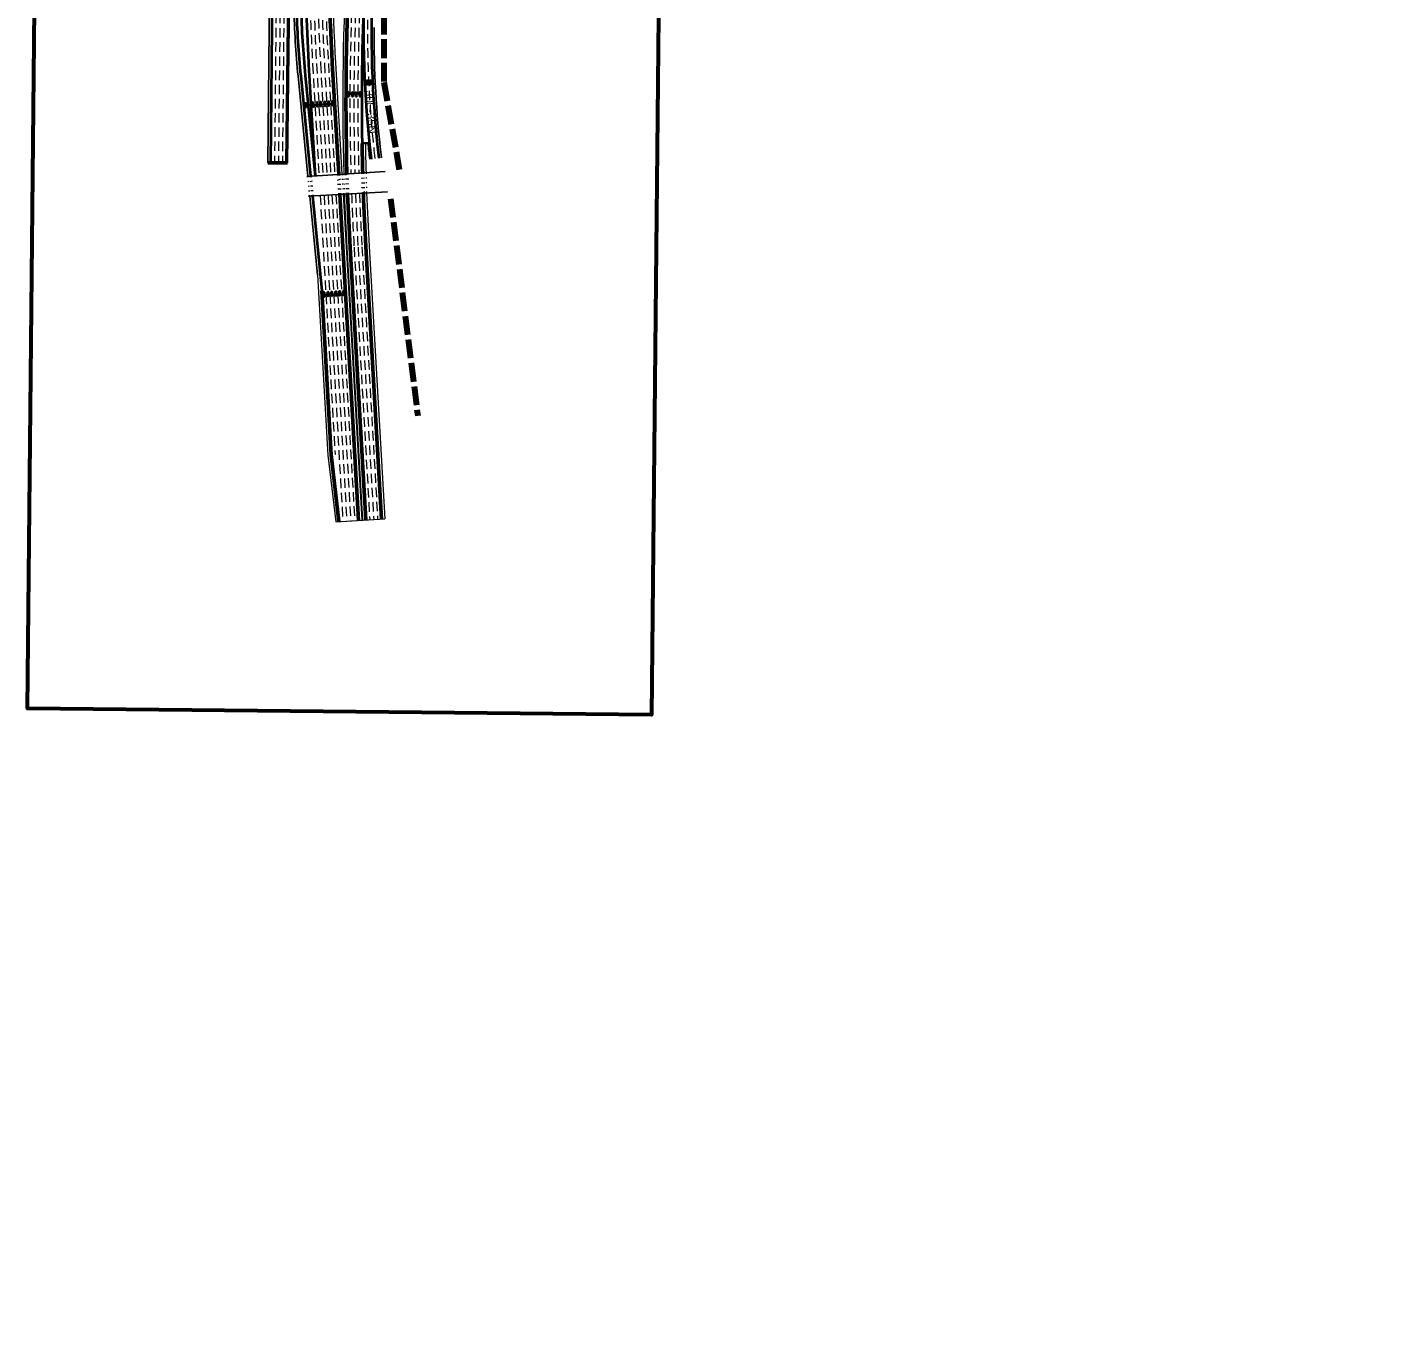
# Model space of a CAD drawing. Extents: x 2329387 to 2347382, y 6951580 to 6987999.
# Drawn here: x 2330661 to 2334841, y 6955545 to 6959510 of the extents above; entities that cross this region are included whole.
import ezdxf
from ezdxf.enums import TextEntityAlignment as Align

# ---------------------------------------------------------------- set-up
doc = ezdxf.new("R2010")
doc.units = 0
doc.header["$LTSCALE"] = 9.6
for name, pattern in [('DOTTED', [1.5, 0.3, -1.2]), ('LONG_DASHED', [7.5, 6, -1.5]), ('MEDIUM_DASHED', [4.5, 3, -1.5])]:
    doc.linetypes.add(name, pattern=pattern)
for name, color, linetype, lineweight in [('26', 7, 'Continuous', 53), ('27', 7, 'Continuous', 40), ('28', 7, 'Continuous', 25), ('41', 7, 'Continuous', 35), ('50', 7, 'MEDIUM_DASHED', 13), ('59', 7, 'LONG_DASHED', 90), ('62', 7, 'Continuous', 60)]:
    doc.layers.add(name, color=color, linetype=linetype, lineweight=lineweight)
doc.layers.add('40', color=7, linetype='Continuous')

msp = doc.modelspace()

# ---------------------------------------------------------------- linework, layer by layer
at = {"layer": '26'}
for p, q in [((2331588.937, 6959401.323), (2331608.461, 6959062.453)), ((2331611.966, 6959001.616), (2331669.16, 6958008.878)), ((2331643.32, 6958839.863), (2331691.118, 6958010.23)), ((2331691.241, 6958842.624), (2331739.028, 6958013.179)), ((2331556.784, 6958707.617), (2331585.543, 6958208.445)), ((2331585.543, 6958208.445), (2331609.305, 6958005.194))]:
    msp.add_line(p, q, dxfattribs=at)
at = {"layer": '26', "lineweight": 13}
for p, q in [((2331598.92, 6959401.898), (2331618.441, 6959063.065)), ((2331621.949, 6959002.176), (2331679.141, 6958009.493)), ((2331633.337, 6958839.288), (2331681.137, 6958009.616)), ((2331701.224, 6958843.199), (2331749.009, 6958013.793)), ((2331543.934, 6958756.798), (2331575.565, 6958207.77))]:
    msp.add_line(p, q, dxfattribs=at)
at = {"layer": '26', "linetype": 'DOTTED'}
msp.add_line((2331608.461, 6959062.453), (2331611.966, 6959001.616), dxfattribs=at)
at = {"layer": '26', "linetype": 'DOTTED', "lineweight": 13}
msp.add_line((2331618.441, 6959063.065), (2331621.949, 6959002.176), dxfattribs=at)
at = {"layer": '26', "lineweight": 13}
msp.add_lwpolyline([(2331575.611, 6958207.284), (2331599.309, 6958004.579), (2331749.009, 6958013.793)], dxfattribs=at)
at = {"layer": '26'}
for centre, radius, start, end in [((2337309.03, 6959730.876), 5729.578, 172.98959, 183.29735), ((2339270.111, 6959279.267), 7639.437, 171.46189, 181.6147), ((2339270.111, 6959279.267), 7591.437, 180.92442, 181.60271), ((2339270.111, 6959279.267), 7639.437, 182.07286, 183.29735), ((2339270.111, 6959279.267), 7591.437, 182.06566, 183.29735)]:
    msp.add_arc(centre, radius, start, end, dxfattribs=at)
at = {"layer": '26', "lineweight": 13}
for centre, radius, start, end in [((2337309.03, 6959730.876), 5719.578, 173.00338, 183.29735), ((2339270.111, 6959279.267), 7649.437, 171.46588, 181.61718), ((2339270.111, 6959279.267), 7581.437, 180.92442, 181.60019), ((2339270.111, 6959279.267), 7649.437, 182.07435, 183.29735), ((2339270.111, 6959279.267), 7581.437, 182.06415, 183.29735)]:
    msp.add_arc(centre, radius, start, end, dxfattribs=at)
at = {"layer": '26', "linetype": 'DOTTED', "lineweight": 13}
for radius, start, end in [(7649.437, 181.61718, 182.07435), (7581.437, 181.60019, 182.06416)]:
    msp.add_arc((2339270.111, 6959279.267), radius, start, end, dxfattribs=at)
at = {"layer": '26', "linetype": 'DOTTED'}
for radius, start, end in [(7639.437, 181.6147, 182.07286), (7591.437, 181.60271, 182.06566)]:
    msp.add_arc((2339270.111, 6959279.267), radius, start, end, dxfattribs=at)
at = {"layer": '27', "lineweight": 25}
for p, q in [((2331398.561, 6959638.076), (2331393.06, 6959098.226)), ((2331458.558, 6959637.465), (2331453.056, 6959097.614)), ((2331484.75, 6959361.704), (2331514.592, 6959056.694)), ((2331737.701, 6959121.932), (2331738.732, 6959113.001)), ((2331520.483, 6958996.484), (2331543.934, 6958756.798))]:
    msp.add_line(p, q, dxfattribs=at)
at = {"layer": '27'}
for p, q in [((2331406.561, 6959637.995), (2331401.059, 6959098.144)), ((2331454.558, 6959637.506), (2331449.057, 6959097.655)), ((2331517.056, 6959397.181), (2331536.642, 6959057.261)), ((2331492.712, 6959362.483), (2331522.582, 6959057.184)), ((2331506.645, 6959363.847), (2331536.642, 6959057.261)), ((2331701.658, 6959157.145), (2331679.661, 6959156.79)), ((2331705.911, 6959118.272), (2331706.943, 6959109.332)), ((2331729.753, 6959121.024), (2331730.785, 6959112.084)), ((2331528.477, 6958996.932), (2331556.784, 6958707.617))]:
    msp.add_line(p, q, dxfattribs=at)
at = {"layer": '27', "lineweight": 53}
msp.add_line((2331393.06, 6959098.226), (2331453.056, 6959097.614), dxfattribs=at)
at = {"layer": '27', "linetype": 'DOTTED', "lineweight": 25}
msp.add_line((2331514.592, 6959056.694), (2331520.483, 6958996.484), dxfattribs=at)
at = {"layer": '27', "linetype": 'DOTTED'}
msp.add_line((2331522.582, 6959057.184), (2331528.477, 6958996.932), dxfattribs=at)
at = {"layer": '27'}
for centre, radius, start, end in [((2339406.145, 6959556.474), 7976, 170.51466, 170.51466), ((2339270.111, 6959279.267), 7591.437, 177.10146, 180.92442), ((2334982.211, 6959496.373), 3298.045, 177.10146, 186.58309), ((2334982.211, 6959496.373), 3274.045, 177.10146, 186.58309), ((2337309.03, 6959730.876), 5801.578, 181.55357, 183.29735), ((2334468.92, 6959653.675), 2990.419, 181.55024, 185.58802), ((2334468.92, 6959653.675), 2976.419, 181.55024, 185.58802)]:
    msp.add_arc(centre, radius, start, end, dxfattribs=at)
at = {"layer": '27', "lineweight": 25}
for centre, radius, start, end in [((2334468.92, 6959653.675), 2998.419, 181.55024, 185.58802), ((2334982.211, 6959496.373), 3266.045, 179.76216, 186.58324), ((2334982.211, 6959496.373), 3302.045, 185.89768, 186.73924)]:
    msp.add_arc(centre, radius, start, end, dxfattribs=at)
at = {"layer": '28'}
for p, q in [((2331511.739, 6959056.519), (2331749.946, 6959071.134)), ((2331515.44, 6958996.201), (2331757.029, 6959009.754))]:
    msp.add_line(p, q, dxfattribs=at)
at = {"layer": '41'}
for points in [[(2331693.08, 6959335.787), (2331696.081, 6959335.817), (2331696.014, 6959342.623), (2331698.451, 6959342.647), (2331694.602, 6959349.81), (2331690.894, 6959342.573), (2331693.013, 6959342.594)], [(2331703.18, 6959335.787), (2331706.181, 6959335.817), (2331706.114, 6959342.623), (2331708.551, 6959342.647), (2331704.702, 6959349.81), (2331700.994, 6959342.573), (2331703.114, 6959342.594)], [(2331528.73, 6959281.194), (2331531.727, 6959281.329), (2331532.035, 6959274.529), (2331534.47, 6959274.64), (2331531.02, 6959267.276), (2331526.92, 6959274.298), (2331529.037, 6959274.394)], [(2331540.742, 6959282.466), (2331543.739, 6959282.602), (2331544.047, 6959275.802), (2331546.482, 6959275.912), (2331543.032, 6959268.549), (2331538.932, 6959275.571), (2331541.049, 6959275.667)], [(2331552.041, 6959283.083), (2331555.039, 6959283.219), (2331555.346, 6959276.419), (2331557.781, 6959276.529), (2331554.332, 6959269.166), (2331550.231, 6959276.188), (2331552.349, 6959276.283)], [(2331564.604, 6959283.608), (2331567.601, 6959283.744), (2331567.909, 6959276.944), (2331570.344, 6959277.054), (2331566.894, 6959269.691), (2331562.794, 6959276.713), (2331564.911, 6959276.808)], [(2331575.748, 6959284.592), (2331578.746, 6959284.727), (2331579.053, 6959277.927), (2331581.488, 6959278.038), (2331578.039, 6959270.674), (2331573.938, 6959277.696), (2331576.056, 6959277.792)], [(2331587.536, 6959285.68), (2331590.533, 6959285.816), (2331590.841, 6959279.016), (2331593.276, 6959279.126), (2331589.826, 6959271.762), (2331585.726, 6959278.785), (2331587.843, 6959278.88)], [(2331636.36, 6959299.928), (2331639.36, 6959299.957), (2331639.294, 6959306.764), (2331641.731, 6959306.788), (2331637.881, 6959313.95), (2331634.173, 6959306.713), (2331636.293, 6959306.734)], [(2331648.423, 6959299.317), (2331651.424, 6959299.347), (2331651.357, 6959306.153), (2331653.794, 6959306.177), (2331649.945, 6959313.34), (2331646.237, 6959306.103), (2331648.357, 6959306.124)], [(2331659.74, 6959299.323), (2331662.74, 6959299.352), (2331662.674, 6959306.159), (2331665.111, 6959306.183), (2331661.261, 6959313.345), (2331657.553, 6959306.109), (2331659.673, 6959306.129)], [(2331672.312, 6959299.489), (2331675.313, 6959299.519), (2331675.246, 6959306.325), (2331677.683, 6959306.349), (2331673.834, 6959313.512), (2331670.126, 6959306.275), (2331672.245, 6959306.296)], [(2331506.376, 6959279.557), (2331509.362, 6959279.849), (2331510.025, 6959273.074), (2331512.451, 6959273.312), (2331509.391, 6959265.778), (2331504.929, 6959272.576), (2331507.039, 6959272.782)], [(2331562.015, 6958703.463), (2331565.012, 6958703.599), (2331565.32, 6958696.799), (2331567.755, 6958696.909), (2331564.305, 6958689.545), (2331560.205, 6958696.567), (2331562.322, 6958696.663)], [(2331574.027, 6958704.736), (2331577.024, 6958704.871), (2331577.332, 6958698.072), (2331579.767, 6958698.182), (2331576.317, 6958690.818), (2331572.217, 6958697.84), (2331574.334, 6958697.936)], [(2331585.326, 6958705.352), (2331588.324, 6958705.488), (2331588.631, 6958698.688), (2331591.066, 6958698.798), (2331587.617, 6958691.435), (2331583.516, 6958698.457), (2331585.634, 6958698.553)], [(2331597.889, 6958705.878), (2331600.886, 6958706.013), (2331601.194, 6958699.213), (2331603.629, 6958699.323), (2331600.179, 6958691.96), (2331596.079, 6958698.982), (2331598.196, 6958699.078)], [(2331609.033, 6958706.861), (2331612.031, 6958706.997), (2331612.338, 6958700.197), (2331614.773, 6958700.307), (2331611.323, 6958692.943), (2331607.223, 6958699.965), (2331609.341, 6958700.061)], [(2331620.82, 6958707.949), (2331623.818, 6958708.085), (2331624.126, 6958701.285), (2331626.561, 6958701.395), (2331623.111, 6958694.032), (2331619.011, 6958701.054), (2331621.128, 6958701.15)]]:
    msp.add_lwpolyline(points, close=True, dxfattribs=at)
at = {"layer": '50'}
for p, q in [((2331418.56, 6959637.873), (2331413.058, 6959098.022)), ((2331430.559, 6959637.75), (2331425.058, 6959097.9)), ((2331442.559, 6959637.628), (2331437.057, 6959097.777)), ((2331529.036, 6959397.871), (2331548.572, 6959058.779)), ((2331541.016, 6959398.562), (2331560.55, 6959059.514)), ((2331552.997, 6959399.252), (2331572.528, 6959060.249)), ((2331564.977, 6959399.942), (2331584.506, 6959060.983)), ((2331576.957, 6959400.632), (2331596.483, 6959061.718)), ((2331717.832, 6959119.648), (2331718.864, 6959110.708)), ((2331552.059, 6958998.255), (2331597.523, 6958209.135)), ((2331564.04, 6958998.927), (2331621.25, 6958005.93)), ((2331576.022, 6958999.6), (2331633.229, 6958006.667)), ((2331588.003, 6959000.272), (2331645.206, 6958007.404)), ((2331599.984, 6959000.944), (2331657.183, 6958008.141)), ((2331655.301, 6958840.553), (2331703.085, 6958011.147)), ((2331667.281, 6958841.243), (2331715.066, 6958011.837)), ((2331679.261, 6958841.934), (2331727.046, 6958012.528))]:
    msp.add_line(p, q, dxfattribs=at)
for centre, radius, start, end in [((2337309.03, 6959730.876), 5765.578, 172.92379, 183.29735), ((2337309.03, 6959730.876), 5753.578, 172.94854, 183.29735), ((2337309.03, 6959730.876), 5741.578, 172.97047, 183.29735), ((2339270.111, 6959279.267), 7627.437, 171.45517, 181.61172), ((2339270.111, 6959279.267), 7615.437, 171.44631, 181.60872), ((2339270.111, 6959279.267), 7603.437, 171.43529, 181.60572), ((2337309.03, 6959730.876), 5789.578, 173.85545, 183.29735), ((2337309.03, 6959730.876), 5777.578, 173.85545, 183.29735), ((2334982.211, 6959496.373), 3286.045, 177.10146, 186.58309), ((2339270.111, 6959279.267), 7627.437, 182.07107, 183.29735), ((2339270.111, 6959279.267), 7615.437, 182.06928, 183.29735), ((2339270.111, 6959279.267), 7603.437, 182.06747, 183.29735)]:
    msp.add_arc(centre, radius, start, end, dxfattribs=at)
at = {"layer": '59'}
msp.add_line((2331766.5, 6958988.5), (2331849, 6958327.5), dxfattribs=at)
msp.add_lwpolyline([(2331746, 6959618.5), (2331746, 6959343.5), (2331793.053, 6959077.812)], dxfattribs=at)
at = {"layer": '62'}
msp.add_lwpolyline([(2332642.295, 6965522.154), (2332560.849, 6957416.973), (2330660.943, 6957436.065), (2330739.467, 6965250.394)], close=True, dxfattribs=at)

# ---------------------------------------------------------------- texts
at = {"layer": '40'}
for rotation, p in [(273.334, (2331690.452, 6959309.007)), (274.719, (2331695.498, 6959238.743))]:
    msp.add_text('3', height=24, rotation=rotation, dxfattribs=at).set_placement(p, align=Align.CENTER)
for s, rotation, width, p in [('0', 273.334, 1.05, (2331691.587, 6959289.524)), ('E', 274.719, 0.8, (2331692.774, 6959271.751)), ('-', 274.719, 1.1, (2331694.174, 6959254.789)), ('5', 274.719, 1.05, (2331697.073, 6959219.671)), ('N', 275.997, 1.1, (2331698.905, 6959197.798))]:
    msp.add_text(s, height=24, rotation=rotation, dxfattribs=dict(at, width=width)).set_placement(p, align=Align.CENTER)

doc.saveas('drawing.dxf')
